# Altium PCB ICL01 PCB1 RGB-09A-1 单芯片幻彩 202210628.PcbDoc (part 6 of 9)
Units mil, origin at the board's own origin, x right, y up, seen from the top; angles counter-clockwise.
Board outline 17436.43 x 6581.89 mil, 2 copper layers (Top Layer, Bottom Layer), stack 65.792 mil thick; 425 components, 516 nets, 1625 pads, 2772 vias.
Unrouted connection lines stored in the file: 1.
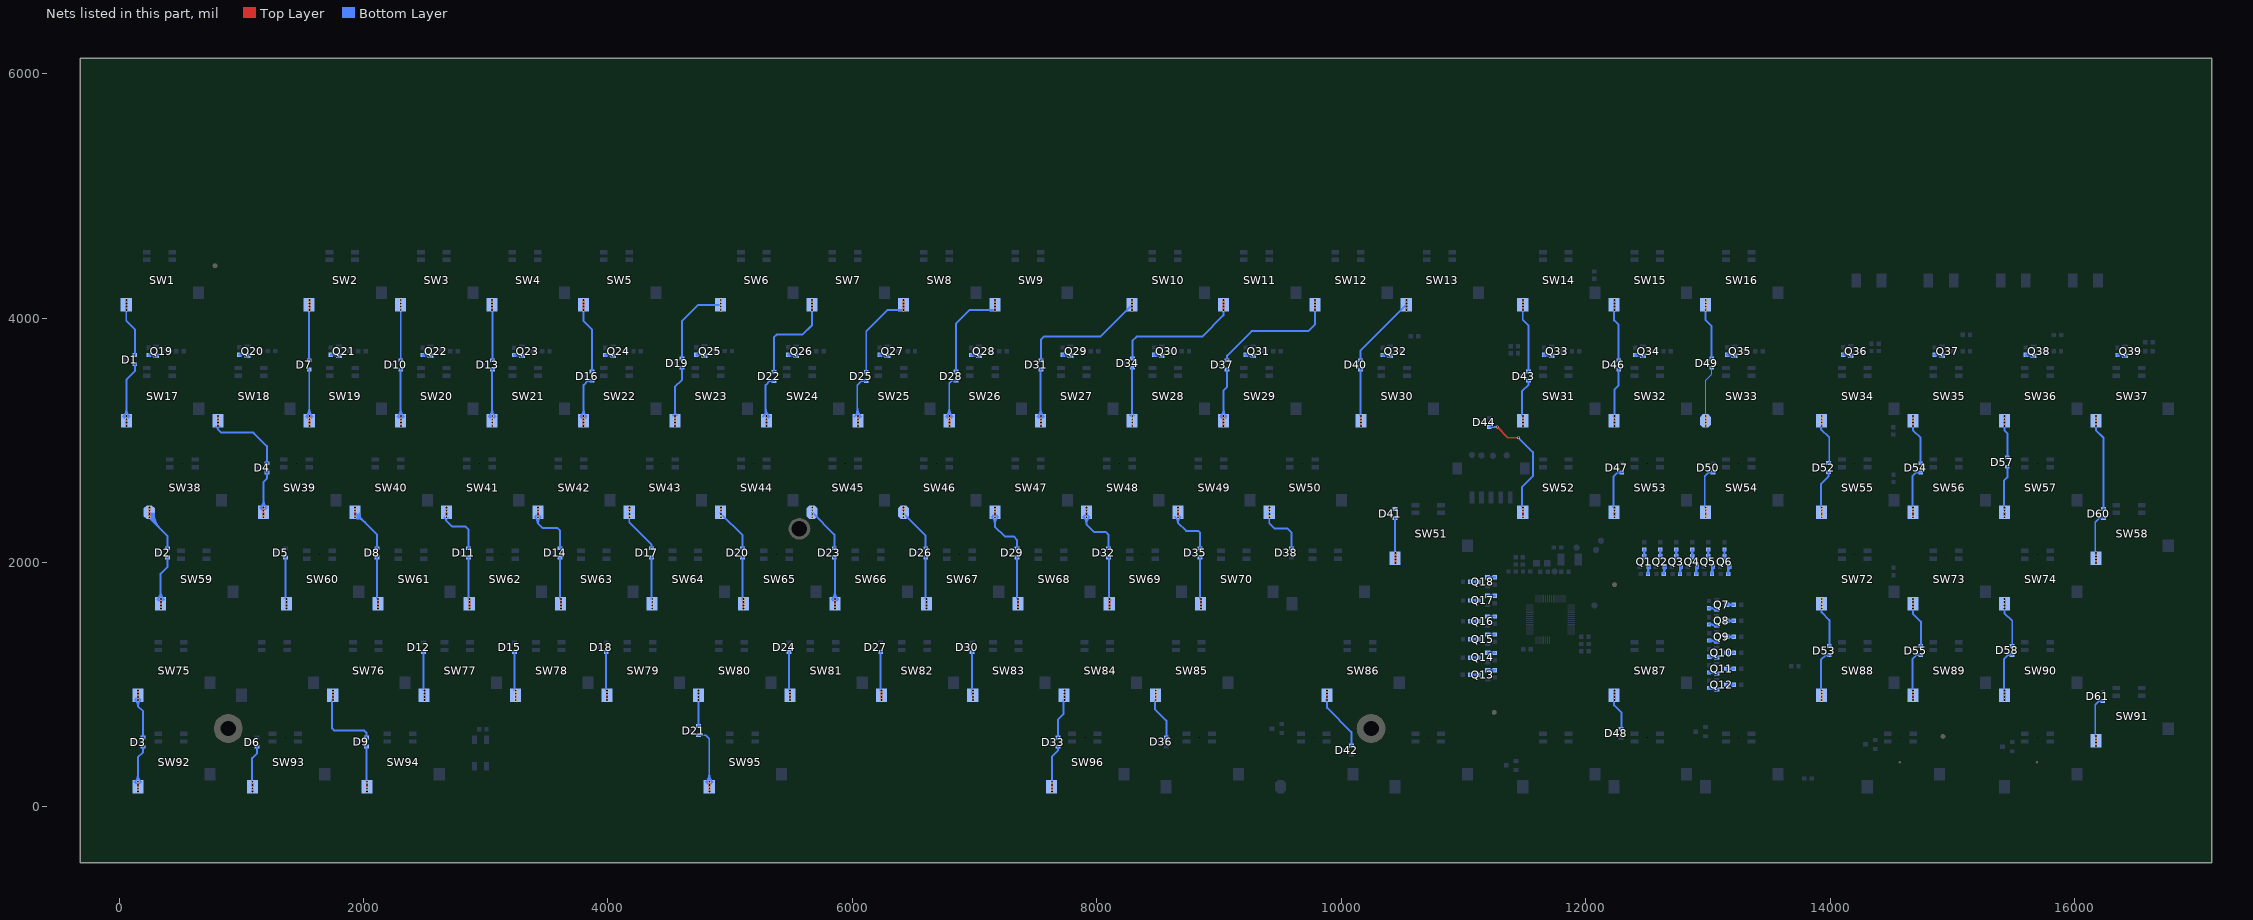
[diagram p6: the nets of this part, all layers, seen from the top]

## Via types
v1: diameter 23.62, hole 15.75, Top Layer to Bottom Layer, tented both sides, 2766 vias
v2: diameter 19.68, hole 11.81, Top Layer to Bottom Layer, tented both sides, 6 vias

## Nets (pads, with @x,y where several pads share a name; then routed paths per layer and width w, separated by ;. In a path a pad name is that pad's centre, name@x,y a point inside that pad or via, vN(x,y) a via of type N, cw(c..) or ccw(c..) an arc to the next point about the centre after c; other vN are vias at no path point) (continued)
NetRL1_2: Q1.B RL1.2 | length 134.2
  Bottom Layer w19.68: RL1.2@12504.25,1912.02 ccw(c12491.5,1924.77) 12509.53,1924.77 ; RL1.2@12509.53,1901.98 12509.53,1960.16 Q1.B@12517.01,1967.65 ; 12509.53,1926.16 ccw(c12529.52,1926.16) RL1.2@12515.38,1912.02 ; 12509.53,1926.22 cw(c12554.79,1926.22) Q1.B@12522.78,1958.22
NetRL2_2: Q2.B RL2.2 | length 121.1
  Bottom Layer w19.68: RL2.2@12634.17,1911.04 ccw(c12619.05,1926.16) 12640.43,1926.16 ; RL2.2@12640.43,1901.98 12640.43,1960.16 Q2.B@12647.92,1967.65 ; 12640.43,1926.22 cw(c12685.69,1926.22) Q2.B@12653.69,1958.22
NetRL3_2: Q3.B RL3.2 | length 121.1
  Bottom Layer w19.68: RL3.2@12766.06,1911.04 ccw(c12750.93,1926.17) 12772.32,1926.17 ; RL3.2@12772.32,1901.98 12772.32,1960.16 Q3.B@12779.81,1967.65 ; 12772.32,1926.22 cw(c12817.58,1926.22) Q3.B@12785.58,1958.22
NetRL4_2: Q4.B RL4.2 | length 134.2
  Bottom Layer w19.68: RL4.2@12897.95,1912.03 ccw(c12885.2,1924.77) 12903.23,1924.77 ; RL4.2@12903.23,1901.98 12903.23,1960.16 Q4.B@12910.72,1967.65 ; 12903.23,1926.16 ccw(c12923.22,1926.16) RL4.2@12909.08,1912.03 ; 12903.23,1926.22 cw(c12948.49,1926.22) Q4.B@12916.48,1958.22
NetRL5_2: Q5.B RL5.2 | length 121.1
  Bottom Layer w19.68: RL5.2@13027.87,1913.01 ccw(c13012.74,1928.13) 13034.13,1928.13 ; RL5.2@13034.13,1901.98 13034.13,1960.16 Q5.B@13041.62,1967.65 ; 13034.13,1926.22 cw(c13079.39,1926.22) Q5.B@13047.39,1958.22
NetRL6_2: Q6.B RL6.2 | length 121.1
  Bottom Layer w19.68: RL6.2@13159.76,1912.03 ccw(c13144.63,1927.15) 13166.02,1927.15 ; RL6.2@13166.02,1901.98 13166.02,1960.16 Q6.B@13173.51,1967.65 ; 13166.02,1926.22 cw(c13211.28,1926.22) Q6.B@13179.28,1958.22
NetRL7_2: Q7.B RL7.2 | length 121.1
  Bottom Layer w19.68: RL7.2@13007.2,1623.93 13065.39,1623.93 Q7.B@13072.87,1616.44 ; RL7.2@13014.3,1630.2 ccw(c13029.42,1645.32) 13029.42,1623.93 ; 13031.45,1623.93 cw(c13031.45,1578.67) Q7.B@13063.45,1610.68
NetRL8_2: Q8.B RL8.2 | length 121.1
  Bottom Layer w19.68: RL8.2@13007.56,1492.53 13065.74,1492.53 Q8.B@13073.23,1485.04 ; RL8.2@13014.65,1498.79 ccw(c13029.78,1513.92) 13029.78,1492.53 ; 13031.8,1492.53 cw(c13031.8,1447.27) Q8.B@13063.81,1479.27
NetRL9_2: Q9.B RL9.2 | length 122.1
  Bottom Layer w19.68: RL9.2@13007.56,1360.64 13065.74,1360.64 Q9.B@13073.23,1353.15 ; RL9.2@13015.79,1367.26 ccw(c13031.78,1383.25) 13031.78,1360.64 ; 13031.8,1360.64 cw(c13031.8,1315.38) Q9.B@13063.81,1347.38
NetRL10_2: Q10.B RL10.2 | length 134.2
  Bottom Layer w19.68: RL10.2@13007.56,1229.73 13065.74,1229.73 Q10.B@13073.23,1222.24 ; RL10.2@13017.61,1223.88 cw(c13031.74,1209.74) 13031.74,1229.73 ; RL10.2@13017.61,1235.01 ccw(c13030.36,1247.76) 13030.36,1229.73 ; 13031.8,1229.73 cw(c13031.8,1184.47) Q10.B@13063.81,1216.48
NetRL11_2: Q11.B RL11.2 | length 121.1
  Bottom Layer w19.68: RL11.2@13007.56,1098.83 13065.74,1098.83 Q11.B@13073.23,1091.34 ; RL11.2@13014.65,1105.09 ccw(c13029.78,1120.21) 13029.78,1098.83 ; 13031.8,1098.83 cw(c13031.8,1053.56) Q11.B@13063.81,1085.57
NetRL12_2: Q12.B RL12.2 | length 131.7
  Bottom Layer w19.68: RL12.2@13007.56,967.92 13065.74,967.92 Q12.B@13073.23,960.43 ; RL12.2@13013.67,978.12 ccw(c13038.3,1002.75) 13038.3,967.92 ; 13031.8,967.92 cw(c13031.8,922.66) Q12.B@13063.81,954.66
NetRL13_2: Q13.B RL13.2 | length 58
  Bottom Layer w19.68: Q13.B@11196.58,1119.6 RL13.2@11254.57,1119.6
NetRL14_2: Q14.B RL14.2 | length 58
  Bottom Layer w19.68: Q14.B@11196.58,1260.23 RL14.2@11254.57,1260.23
NetRL15_2: Q15.B RL15.2 | length 58
  Bottom Layer w19.68: Q15.B@11196.58,1410.85 RL15.2@11254.57,1410.85
NetRL16_2: Q16.B RL16.2 | length 58
  Bottom Layer w19.68: Q16.B@11196.58,1558.37 RL16.2@11254.57,1558.37
NetRL17_2: Q17.B RL17.2 | length 58
  Bottom Layer w19.68: Q17.B@11196.58,1727.44 RL17.2@11254.57,1727.44
NetRL18_2: Q18.B RL18.2 | length 58
  Bottom Layer w19.68: Q18.B@11196.58,1878.18 RL18.2@11254.57,1878.18
NetRL19_2: Q19.B RL19.2 | length 128.3
  Bottom Layer w19.68: RL19.2@242.98,3697.46 298.44,3697.46 Q19.B@305.16,3690.75 ; RL19.2@248.55,3691.9 cw(c261.99,3678.45) 261.99,3697.46 cw(c261.99,3716.47) RL19.2@248.55,3703.03 ; 263.63,3697.46 cw(c263.63,3654.84) Q19.B@293.77,3684.98
NetRL20_2: Q20.B RL20.2 | length 135.8
  Bottom Layer w19.68: RL20.2@985.11,3699.92 1042.05,3699.92 Q20.B@1050.24,3691.73 ; RL20.2@990.68,3694.35 cw(c1004.12,3680.91) 1004.12,3699.92 cw(c1004.12,3718.93) RL20.2@990.68,3705.48 ; 1005.16,3699.92 cw(c1005.16,3652.28) Q20.B@1038.84,3685.96
NetRL21_2: Q21.B RL21.2 | length 126.1
  Bottom Layer w19.68: RL21.2@1734.13,3699.92 1791.07,3699.92 Q21.B@1799.25,3691.73 ; RL21.2@1737.72,3693.37 cw(c1753.54,3677.55) 1753.54,3699.92 ; 1751.8,3699.92 cw(c1751.8,3648.92) Q21.B@1787.86,3684.98
NetRL22_2: Q22.B RL22.2 | length 156.3
  Bottom Layer w19.68: RL22.2@2483.14,3699.92 2540.08,3699.92 Q22.B@2548.27,3691.73 ; RL22.2@2490.43,3691.38 cw(c2508.34,3664.23) 2516.76,3695.64 ; RL22.2@2491.66,3692.38 cw(c2509.85,3674.19) 2509.85,3699.92 ; RL22.2@2500.81,3699.92 cw(c2500.81,3648.92) Q22.B@2536.88,3684.98
NetRL23_2: Q23.B RL23.2 | length 158
  Bottom Layer w19.68: RL23.2@3232.16,3699.92 3289.1,3699.92 Q23.B@3297.28,3691.73 ; RL23.2@3236.52,3691.39 cw(c3255.59,3662.75) 3264.49,3695.99 ; RL23.2@3237.72,3692.38 cw(c3255.92,3674.19) 3255.92,3699.92 ; RL23.2@3249.83,3699.92 cw(c3249.83,3648.92) Q23.B@3285.89,3684.98
NetRL24_2: Q24.B RL24.2 | length 128.8
  Bottom Layer w19.68: RL24.2@3979.2,3699.92 4036.14,3699.92 Q24.B@4044.33,3691.73 ; RL24.2@3983.79,3692.38 cw(c4001.98,3674.19) 4001.98,3699.92 ; 3996.88,3699.92 cw(c3996.88,3648.92) Q24.B@4032.94,3684.98
NetRL25_2: Q25.B RL25.2 | length 133.2
  Bottom Layer w19.68: RL25.2@4726.25,3699.92 4783.19,3699.92 Q25.B@4791.38,3691.73 ; RL25.2@4727.88,3694.35 cw(c4741.32,3680.91) 4741.32,3699.92 cw(c4741.32,3718.93) RL25.2@4727.88,3705.48 ; 4748.68,3699.92 cw(c4748.68,3655.64) Q25.B@4779.99,3686.95
NetRL26_2: Q26.B RL26.2 | length 165.6
  Bottom Layer w19.68: RL26.2@5475.27,3699.92 5532.21,3699.92 Q26.B@5540.39,3691.73 ; RL26.2@5479.2,3693.1 cw(c5496.52,3663.11) 5505.48,3696.56 ; RL26.2@5480.83,3694.35 cw(c5494.28,3680.91) 5494.28,3699.92 cw(c5494.28,3718.93) RL26.2@5480.83,3705.48 ; RL26.2@5492.94,3699.92 cw(c5492.94,3648.92) Q26.B@5529,3684.98
NetRL27_2: Q27.B RL27.2 | length 154.5
  Bottom Layer w19.68: RL27.2@6221.33,3699.92 6278.27,3699.92 Q27.B@6286.46,3691.73 ; RL27.2@6227.24,3692.11 cw(c6245.3,3660.82) 6254.65,3695.72 ; RL27.2@6228.87,3693.37 cw(c6244.68,3677.55) 6244.68,3699.92 ; RL27.2@6239,3699.92 cw(c6239,3648.92) Q27.B@6275.06,3684.98
NetRL28_2: Q28.B RL28.2 | length 156.3
  Bottom Layer w19.68: RL28.2@6970.35,3699.92 7027.29,3699.92 Q28.B@7035.47,3691.73 ; RL28.2@6977.64,3691.38 cw(c6995.55,3664.23) 7003.96,3695.64 ; RL28.2@6978.87,3692.38 cw(c6997.06,3674.19) 6997.06,3699.92 ; RL28.2@6988.02,3699.92 cw(c6988.02,3648.92) Q28.B@7024.08,3684.98
NetRL29_2: Q29.B RL29.2 | length 155.9
  Bottom Layer w19.68: RL29.2@7720.35,3699.92 7777.29,3699.92 Q29.B@7785.47,3691.73 ; RL29.2@7724.28,3692.11 cw(c7743.22,3659.32) 7753.02,3695.9 ; RL29.2@7725.91,3693.37 cw(c7741.73,3677.55) 7741.73,3699.92 ; RL29.2@7738.02,3699.92 cw(c7738.02,3648.92) Q29.B@7774.08,3684.98
NetRL30_2: Q30.B RL30.2 | length 153.8
  Bottom Layer w19.68: RL30.2@8466.41,3699.92 8523.35,3699.92 Q30.B@8531.53,3691.73 ; RL30.2@8473.3,3692.11 cw(c8490.93,3661.58) 8500.06,3695.64 ; RL30.2@8474.93,3693.37 cw(c8490.75,3677.55) 8490.75,3699.92 ; RL30.2@8484.08,3699.92 cw(c8484.08,3648.92) Q30.B@8520.14,3684.98
NetRL31_2: Q31.B RL31.2 | length 153.2
  Bottom Layer w19.68: RL31.2@9214.44,3699.92 9271.38,3699.92 Q31.B@9279.57,3691.73 ; RL31.2@9222.31,3692.11 cw(c9239.51,3662.33) 9248.41,3695.55 ; RL31.2@9223.94,3693.37 cw(c9239.76,3677.55) 9239.76,3699.92 ; RL31.2@9232.11,3699.92 cw(c9232.11,3648.92) Q31.B@9268.17,3684.98
NetRL32_2: Q32.B RL32.2 | length 156.3
  Bottom Layer w19.68: RL32.2@10336.49,3699.92 10393.43,3699.92 Q32.B@10401.61,3691.73 ; RL32.2@10343.78,3691.38 cw(c10361.69,3664.23) 10370.1,3695.65 ; RL32.2@10345.01,3692.38 cw(c10363.2,3674.19) 10363.2,3699.92 ; RL32.2@10354.16,3699.92 cw(c10354.16,3648.92) Q32.B@10390.22,3684.98
NetRL33_2: Q33.B RL33.2 | length 154.5
  Bottom Layer w19.68: RL33.2@11656.37,3699.92 11713.31,3699.92 Q33.B@11721.5,3691.73 ; RL33.2@11662.27,3692.11 cw(c11680.34,3660.82) 11689.69,3695.72 ; RL33.2@11663.91,3693.37 cw(c11679.72,3677.55) 11679.72,3699.92 ; RL33.2@11674.04,3699.92 cw(c11674.04,3648.92) Q33.B@11710.1,3684.98
NetRL34_2: Q34.B RL34.2 | length 158
  Bottom Layer w19.68: RL34.2@12404.4,3699.92 12461.34,3699.92 Q34.B@12469.53,3691.73 ; RL34.2@12408.76,3691.39 cw(c12427.83,3662.75) 12436.74,3695.99 ; RL34.2@12409.97,3692.38 cw(c12428.16,3674.19) 12428.16,3699.92 ; RL34.2@12422.07,3699.92 cw(c12422.07,3648.92) Q34.B@12458.14,3684.98
NetRL35_2: Q35.B RL35.2 | length 146.4
  Bottom Layer w19.68: RL35.2@13152.43,3699.92 13209.37,3699.92 Q35.B@13217.56,3691.73 ; RL35.2@13161.29,3694.08 cw(c13175.86,3668.85) 13183.4,3696.99 ; RL35.2@13162.92,3706.47 ccw(c13178.74,3722.29) 13178.74,3699.92 ; RL35.2@13172.48,3699.92 cw(c13172.48,3652.28) Q35.B@13206.17,3685.96
NetRL36_2: Q36.B RL36.2 | length 120.9
  Bottom Layer w19.68: RL36.2@14104.2,3699.92 14161.14,3699.92 Q36.B@14169.33,3691.73 ; RL36.2@14111.74,3706.47 ccw(c14127.56,3722.29) 14127.56,3699.92 ; 14126.63,3699.92 cw(c14126.63,3655.64) Q36.B@14157.94,3686.95
NetRL37_2: Q37.B RL37.2 | length 123.5
  Bottom Layer w19.68: RL37.2@14851.25,3699.92 14908.19,3699.92 Q37.B@14916.38,3691.73 ; RL37.2@14858.79,3693.37 cw(c14874.61,3677.55) 14874.61,3699.92 ; 14871.3,3699.92 cw(c14871.3,3652.28) Q37.B@14904.99,3685.96
NetRL38_2: Q38.B RL38.2 | length 153.8
  Bottom Layer w19.68: RL38.2@15598.3,3699.92 15655.24,3699.92 Q38.B@15663.42,3691.73 ; RL38.2@15605.19,3692.11 cw(c15622.82,3661.57) 15631.95,3695.64 ; RL38.2@15606.82,3693.37 cw(c15622.64,3677.55) 15622.64,3699.92 ; RL38.2@15615.97,3699.92 cw(c15615.97,3648.92) Q38.B@15652.03,3684.98
NetRL39_2: Q39.B RL39.2 | length 129.8
  Bottom Layer w19.68: RL39.2@16350.27,3697.95 16405.24,3697.95 Q39.B@16412.44,3690.75 ; RL39.2@16355.83,3692.38 cw(c16369.28,3678.94) 16369.28,3697.95 cw(c16369.28,3716.96) RL39.2@16355.83,3703.52 ; 16369.74,3697.95 cw(c16369.74,3653.67) Q39.B@16401.05,3684.98
NetRR1_1: Q1.C RR1.1 | length 58
  Bottom Layer w19.68: Q1.C@12479.01,2047.65 RR1.1@12479.01,2105.61
NetRR2_1: Q2.C RR2.1 | length 58
  Bottom Layer w19.68: Q2.C@12609.92,2047.65 RR2.1@12609.92,2105.61
NetRR3_1: Q3.C RR3.1 | length 58
  Bottom Layer w19.68: Q3.C@12741.81,2047.65 RR3.1@12741.81,2105.61
NetRR4_1: Q4.C RR4.1 | length 58
  Bottom Layer w19.68: Q4.C@12872.72,2047.65 RR4.1@12872.69,2105.61
NetRR5_1: Q5.C RR5.1 | length 58
  Bottom Layer w19.68: Q5.C@13003.62,2047.65 RR5.1@13003.62,2105.61
NetRR6_1: Q6.C RR6.1 | length 58
  Bottom Layer w19.68: Q6.C@13135.51,2047.65 RR6.1@13135.51,2105.61
NetRR7_1: Q7.C RR7.1 | length 59.5
  Bottom Layer w19.68: Q7.C@13152.87,1654.44 RR7.1@13212.34,1654.44
NetRR8_1: Q8.C RR8.1 | length 59.1
  Bottom Layer w19.68: Q8.C@13153.23,1523.04 RR8.1@13212.34,1523.08
NetRR9_1: Q9.C RR9.1 | length 59.1
  Bottom Layer w19.68: Q9.C@13153.23,1391.15 RR9.1@13212.34,1391.15
NetRR10_1: Q10.C RR10.1 | length 59.1
  Bottom Layer w19.68: Q10.C@13153.23,1260.24 RR10.1@13212.34,1260.24
NetRR11_1: Q11.C RR11.1 | length 59.1
  Bottom Layer w19.68: Q11.C@13153.23,1129.34 RR11.1@13212.34,1129.34
NetRR12_1: Q12.C RR12.1 | length 59.1
  Bottom Layer w19.68: Q12.C@13153.23,998.43 RR12.1@13212.34,998.43
NetRR13_1: Q13.C RR13.1 | length 64.2
  Bottom Layer w19.68: RR13.1@11055.07,1082.02 Q13.C@11119.23,1082.02
NetRR14_1: Q14.C RR14.1 | length 63.8
  Bottom Layer w19.68: RR14.1@11055.09,1222.3 Q14.C@11118.87,1222.3
NetRR15_1: Q15.C RR15.1 | length 63.7
  Bottom Layer w19.68: RR15.1@11055.55,1373.12 Q15.C@11119.23,1373.12
NetRR16_1: Q16.C RR16.1 | length 61
  Bottom Layer w19.68: RR16.1@11055.53,1520.37 Q16.C@11116.58,1520.37
NetRR17_1: Q17.C RR17.1 | length 61.1
  Bottom Layer w19.68: RR17.1@11055.5,1689.42 Q17.C@11116.58,1689.42
NetRR18_1: Q18.C RR18.1 | length 61
  Bottom Layer w19.68: RR18.1@11055.6,1842.12 Q18.C@11116.58,1842.12
NetSW1_2: D1.K1 SW1.2 | length 519.2
  Top Layer w15.75: v1(60.78,4067.09) v1(60.78,4147.08)
  Bottom Layer w15.75: SW1.2@59.52,4107.08 59.52,3977.97 129.23,3908.26 D1.K1@129.23,3696.72
  other v1: 60.78,4093.75 60.78,4120.42
NetSW2_2: D7.K1 SW2.2 | length 492.7
  Top Layer w15.75: v1(1556.84,4067.09) v1(1556.84,4093.75) v1(1556.84,4120.42) ; v1@1557.5,4120.41 v1@1557.83,4147.07
  Bottom Layer w15.75: D7.K1@1555.58,3654.37 SW2.2@1555.58,4067.09
  other v1: 1556.84,4147.08
NetSW3_2: D10.K1 SW3.2 | length 493.1
  Top Layer w15.75: v1(2304.87,4147.08) v1(2304.87,4120.42) v1(2304.87,4093.75) 2304.87,4068.07 v1@2305.86,4067.09
  Bottom Layer w15.75: D10.K1@2305.38,3654.37 SW3.2@2305.38,4067.09
  other v1: 2304.87,4067.09
NetSW4_2: D13.K1 SW4.2 | length 492.7
  Top Layer w15.75: v1(3052.9,4067.09) v1(3052.9,4093.75) v1(3052.9,4120.42) v1(3052.9,4147.08)
  Bottom Layer w15.75: D13.K1@3056.25,3654.37 SW4.2@3056.25,4067.09
NetSW5_2: D16.K1 SW5.2 | length 613.8
  Top Layer w15.75: v1(3800.94,4067.09) v1(3800.94,4093.75) v1(3800.94,4120.42) v1(3800.94,4147.08)
  Bottom Layer w15.75: SW5.2@3799.68,4067.09 3799.68,3976.98 3869.41,3907.25 D16.K1@3869.41,3562.15
NetSW6_2: D19.K1 SW6.2 | length 758
  Top Layer w15.75: v1(4922.98,4067.09) v1(4922.98,4093.75) v1(4922.98,4120.42) v1(4922.98,4147.08)
  Bottom Layer w15.75: D19.K1@4605.63,3667.82 4605.63,3974.94 4737.77,4107.08 SW6.2@4921.72,4107.08
NetSW7_2: D22.K1 SW7.2 | length 839.1
  Top Layer w15.75: v1(5671.02,4067.09) v1(5671.02,4093.75) v1(5671.02,4120.42) v1(5671.02,4147.08)
  Bottom Layer w15.75: D22.K1@5358.17,3560.73 5358.17,3840.96 5380.81,3863.59 5591.97,3863.59 5669.76,3941.37 SW7.2@5669.76,4067.09
NetSW8_2: D25.K1 SW8.2 | length 787.7
  Top Layer w15.75: v1(6419.05,4067.09) v1(6419.05,4093.75) v1(6419.05,4120.42) v1(6419.05,4147.08)
  Bottom Layer w15.75: D25.K1@6113.5,3561.17 6113.5,3892.03 6288.56,4067.09 SW8.2@6417.79,4067.09
NetSW9_2: D28.K1 SW9.2 | length 838.1
  Top Layer w15.75: v1(7167.08,4067.09) v1(7167.08,4093.75) v1(7167.08,4120.42) v1(7167.08,4147.08)
  Bottom Layer w15.75: D28.K1@6848.51,3561.83 6848.51,3957.02 6958.57,4067.09 SW9.2@7165.82,4067.09
NetSW10_2: D31.K1 SW10.2 | length 1103.8
  Top Layer w15.75: v1(8289.13,4147.08) v1(8289.13,4120.42) v1(8289.13,4093.75) 8289.13,4068.07 v1@8290.11,4067.09
  Bottom Layer w15.75: D31.K1@7543.87,3654.76 7543.87,3826.42 7566.27,3848.83 8029.61,3848.83 SW10.2@8281.83,4101.05
  other v1: 8289.13,4067.09
NetSW11_2: D34.K1 SW11.2 | length 1101.5
  Top Layer w15.75: v1(9037.16,4067.09) v1(9037.16,4093.75) v1(9037.16,4120.42) v1(9037.16,4147.08)
  Bottom Layer w15.75: D34.K1@8291.3,3667.66 8291.3,3812.77 8326.37,3847.84 8861.77,3847.84 9035.9,4021.97 SW11.2@9035.9,4067.09
NetSW12_2: D37.K1 SW12.2 | length 1102.3
  Top Layer w15.75: v1(9785.19,4067.09) v1(9785.19,4093.75) v1(9785.19,4120.42) v1(9785.19,4147.08)
  Bottom Layer w15.75: D37.K1@9066.26,3654.37 9066.26,3691.98 9267.04,3892.75 9731.83,3892.75 9783.93,3944.85 SW12.2@9783.93,4107.08
NetSW13_2: D40.K1 SW13.2 | length 680
  Top Layer w15.75: v1(10533.22,4147.08) v1(10533.22,4120.42) v1(10533.22,4093.75) 10533.22,4068.07 v1@10534.2,4067.09
  Bottom Layer w15.75: D40.K1@10158.34,3654.37 10158.34,3735.82 SW13.2@10524.74,4102.23
  other v1: 10533.22,4067.09
NetSW14_2: D43.K1 SW14.2 | length 605.5
  Top Layer w15.75: v1(11485.98,4067.09) v1(11485.98,4093.75) v1(11485.98,4120.42) v1(11485.98,4147.08)
  Bottom Layer w15.75: SW14.2@11484.72,4067.09 11484.72,3985.84 11532.69,3937.87 D43.K1@11532.69,3561.47
NetSW15_2: D46.K1 SW15.2 | length 508.1
  Top Layer w15.75: v1(12234.01,4067.09) v1(12234.01,4093.75) v1(12234.01,4120.42) v1(12234.01,4147.08)
  Bottom Layer w15.75: SW15.2@12232.75,4067.09 12232.75,3980.92 12269.77,3943.9 D46.K1@12269.77,3654.37
NetSW16_2: D49.K1 SW16.2 | length 500
  Top Layer w15.75: v1(12982.04,4067.09) v1(12982.04,4093.75) v1(12982.04,4120.42) v1(12982.04,4147.08)
  Bottom Layer w15.75: SW16.2@12980.78,4067.09 12980.78,3982.89 13030.83,3932.84 D49.K1@13030.83,3667.82
NetSW17_2: D1.K2 SW17.2 | length 816.1
  Top Layer w15.75: v1(61.76,3118.27) v1(61.76,3144.93) v1(61.76,3171.6) v1(61.76,3198.27)
  Bottom Layer w15.75: SW17.2@34.06,3194.56 ccw(c-29.79,3258.4) 60.5,3258.4 ccw(c150.8,3258.4) SW17.2@86.95,3194.56 ; SW17.2@44.94,3183.05 cw(c67.4,3167.55) SW17.2@62.47,3194.39 ; SW17.2@45.19,3183.42 ccw(c8.23,3220.38) 60.5,3220.38 ccw(c112.78,3220.38) SW17.2@75.81,3183.42 ; SW17.2@58.93,3201 ccw(c49.59,3209.99) SW17.2@62.23,3212.9 ; SW17.2@60.5,3198.27 60.5,3495.6 129.23,3564.32 D1.K2@129.23,3621.72 ; SW17.2@60.5,3210.81 ccw(c74.31,3210.81) SW17.2@64.55,3201.05 ; SW17.2@61.11,3194.38 cw(c57.93,3175.47) SW17.2@73.55,3186.6
NetSW18_2: D4.K1 SW18.2 | length 823.3
  Top Layer w15.75: v1(809.8,3118.27) v1(809.8,3144.93) v1(809.8,3171.6) v1(809.8,3198.27)
  Bottom Layer w15.75: SW18.2@793.27,3114.28 cw(c783.28,3091.93) 807.75,3091.93 cw(c831.23,3091.93) SW18.2@822.48,3113.72 ; SW18.2@807.35,3115.18 cw(c798.99,3104.65) 811.08,3098.75 ; SW18.2@807.75,3103.83 cw(c824.23,3103.83) SW18.2@812.58,3115.48 ; SW18.2@807.75,3118.27 807.75,3091.94 837.38,3062.31 1099.76,3062.31 1210.31,2951.76 D4.K1@1210.31,2812.51 ; D4.K1@1204.75,2818.08 ccw(c1191.3,2831.52) 1210.31,2831.52 ccw(c1229.32,2831.52) D4.K1@1215.88,2818.08
NetSW19_2: D7.K2 SW19.2 | length 745.3
  Top Layer w15.75: v1(1557.83,3118.27) v1(1557.83,3144.93) v1(1557.83,3171.6) v1(1557.83,3198.27)
  Bottom Layer w15.75: SW19.2@1530.12,3194.56 ccw(c1466.27,3258.4) 1556.57,3258.4 ccw(c1646.86,3258.4) SW19.2@1583.01,3194.56 ; SW19.2@1541,3183.05 cw(c1563.46,3167.55) SW19.2@1558.54,3194.39 ; SW19.2@1541.25,3183.42 ccw(c1504.29,3220.38) 1556.57,3220.38 ccw(c1608.84,3220.38) SW19.2@1571.88,3183.42 ; SW19.2@1554.99,3201 ccw(c1545.66,3209.99) SW19.2@1558.29,3212.9 ; SW19.2@1556.57,3198.27 D7.K2@1556.57,3579.37 ; SW19.2@1556.57,3210.81 ccw(c1570.37,3210.81) SW19.2@1560.61,3201.05 ; SW19.2@1557.17,3194.38 cw(c1554,3175.47) SW19.2@1569.61,3186.6
NetSW20_2: D10.K2 SW20.2 | length 745.3
  Top Layer w15.75: v1(2305.86,3118.27) v1(2305.86,3144.93) v1(2305.86,3171.6) v1(2305.86,3198.27)
  Bottom Layer w15.75: SW20.2@2278.15,3194.56 ccw(c2214.3,3258.4) 2304.6,3258.4 ccw(c2394.89,3258.4) SW20.2@2331.04,3194.56 ; SW20.2@2289.03,3183.05 cw(c2311.49,3167.55) SW20.2@2306.57,3194.39 ; SW20.2@2289.29,3183.42 ccw(c2252.32,3220.38) 2304.6,3220.38 ccw(c2356.87,3220.38) SW20.2@2319.91,3183.42 ; SW20.2@2303.02,3201 ccw(c2293.69,3209.99) SW20.2@2306.32,3212.9 ; SW20.2@2304.6,3198.27 D10.K2@2304.6,3579.37 ; SW20.2@2304.6,3210.81 ccw(c2318.4,3210.81) SW20.2@2308.64,3201.05 ; SW20.2@2305.21,3194.38 cw(c2302.03,3175.47) SW20.2@2317.65,3186.6
NetSW21_2: D13.K2 SW21.2 | length 745.3
  Top Layer w15.75: v1(3053.89,3118.27) v1(3053.89,3144.93) v1(3053.89,3171.6) v1(3053.89,3198.27)
  Bottom Layer w15.75: SW21.2@3026.18,3194.56 ccw(c2962.33,3258.4) 3052.63,3258.4 ccw(c3142.92,3258.4) SW21.2@3079.08,3194.56 ; SW21.2@3037.06,3183.05 cw(c3059.52,3167.55) SW21.2@3054.6,3194.39 ; SW21.2@3037.32,3183.42 ccw(c3000.35,3220.38) 3052.63,3220.38 ccw(c3104.91,3220.38) SW21.2@3067.94,3183.42 ; SW21.2@3051.05,3201 ccw(c3041.72,3209.99) SW21.2@3054.35,3212.9 ; SW21.2@3052.63,3198.27 D13.K2@3052.63,3579.37 ; SW21.2@3052.63,3210.81 ccw(c3066.44,3210.81) SW21.2@3056.67,3201.05 ; SW21.2@3053.24,3194.38 cw(c3050.06,3175.47) SW21.2@3065.68,3186.6
NetSW22_2: D16.K2 SW22.2 | length 730.8
  Top Layer w15.75: v1(3801.92,3118.27) v1(3801.92,3144.93) v1(3801.92,3171.6) v1(3801.92,3198.27)
  Bottom Layer w15.75: SW22.2@3774.21,3194.56 ccw(c3710.37,3258.4) 3800.66,3258.4 ccw(c3890.96,3258.4) SW22.2@3827.11,3194.56 ; SW22.2@3785.09,3183.05 cw(c3807.56,3167.55) SW22.2@3802.63,3194.39 ; SW22.2@3785.35,3183.42 ccw(c3748.38,3220.38) 3800.66,3220.38 ccw(c3852.94,3220.38) SW22.2@3815.97,3183.42 ; SW22.2@3799.09,3201 ccw(c3789.75,3209.99) SW22.2@3802.38,3212.9 ; SW22.2@3800.66,3198.27 3800.66,3450.99 3836.2,3486.52 D16.K2@3870.04,3486.52 ; SW22.2@3800.66,3210.81 ccw(c3814.47,3210.81) SW22.2@3804.7,3201.05 ; SW22.2@3801.27,3194.38 cw(c3798.09,3175.47) SW22.2@3813.71,3186.6 ; D16.K2@3860.53,3480.96 ccw(c3847.09,3467.51) 3847.09,3486.52 ccw(c3847.09,3505.53) D16.K2@3860.53,3492.09
NetSW23_2: D19.K2 SW23.2 | length 612.5
  Top Layer w15.75: v1(4549.95,3118.27) v1(4549.95,3144.93) v1(4549.95,3171.6) v1(4549.95,3198.27)
  Bottom Layer w15.75: SW23.2@4534.08,3202.54 ccw(c4524.72,3224.61) 4548.69,3224.61 ccw(c4572.66,3224.61) SW23.2@4563.3,3202.54 ; SW23.2@4547.81,3201.57 ccw(c4541.15,3211.84) 4552.24,3217.03 ; SW23.2@4548.69,3198.27 4548.69,3436.05 4605.63,3492.98 D19.K2@4605.63,3592.82 ; SW23.2@4548.69,3210.81 ccw(c4562.5,3210.81) SW23.2@4552.74,3201.05 ; D19.K2@4600.06,3587.26 cw(c4586.62,3573.81) 4605.63,3573.81 cw(c4624.64,3573.81) D19.K2@4611.2,3587.26
NetSW24_2: D22.K2 SW24.2 | length 696.3
  Top Layer w15.75: v1(5297.98,3118.27) v1(5297.98,3144.93) v1(5297.98,3171.6) v1(5297.98,3198.27)
  Bottom Layer w15.75: SW24.2@5270.28,3194.56 ccw(c5220.19,3244.64) 5291.02,3244.64 ; SW24.2@5291.02,3198.27 5291.02,3451.19 5325.56,3485.73 D22.K2@5358.17,3485.73 ; 5291.02,3224.58 ccw(c5324.3,3224.58) SW24.2@5300.77,3201.05 ; 5291.02,3234.15 ccw(c5362.77,3234.15) SW24.2@5312.04,3183.42 ; 5291.02,3272.17 ccw(c5400.79,3272.17) SW24.2@5323.17,3194.56 ; SW24.2@5294.56,3200.22 ccw(c5278.1,3209.6) 5296.38,3214.6 ; SW24.2@5297.49,3194.36 cw(c5295.45,3178.17) SW24.2@5308.35,3188.17 ; D22.K2@5348.67,3480.16 ccw(c5335.23,3466.72) 5335.23,3485.73 ccw(c5335.23,3504.74) D22.K2@5348.67,3491.3
NetSW25_2: D25.K2 SW25.2 | length 697.9
  Top Layer w15.75: v1(6046.02,3118.27) v1(6046.02,3144.93) v1(6046.02,3171.6) v1(6046.02,3198.27)
  Bottom Layer w15.75: SW25.2@6018.31,3194.56 ccw(c5965.85,3247.02) 6040.04,3247.02 ; SW25.2@6040.04,3198.27 6040.04,3450.21 6075.37,3485.54 D25.K2@6114.13,3485.54 ; 6040.04,3222.2 ccw(c6069.95,3222.2) SW25.2@6048.8,3201.05 ; 6040.04,3231.77 ccw(c6108.42,3231.77) SW25.2@6060.07,3183.42 ; 6040.04,3269.79 ccw(c6146.44,3269.79) SW25.2@6071.2,3194.56 ; SW25.2@6042.61,3200.23 ccw(c6025.8,3209.94) 6044.54,3214.96 ; SW25.2@6045.5,3194.36 cw(c6043.32,3177.8) SW25.2@6056.58,3187.97 ; D25.K2@6104.63,3479.97 ccw(c6091.19,3466.53) 6091.19,3485.54 ccw(c6091.19,3504.55) D25.K2@6104.63,3491.11
NetSW26_2: D28.K2 SW26.2 | length 727.1
  Top Layer w15.75: v1(6794.05,3118.27) v1(6794.05,3144.93) v1(6794.05,3171.6) v1(6794.05,3198.27)
  Bottom Layer w15.75: SW26.2@6766.34,3194.56 ccw(c6702.49,3258.4) 6792.79,3258.4 ccw(c6883.08,3258.4) SW26.2@6819.23,3194.56 ; SW26.2@6777.22,3183.05 cw(c6799.68,3167.55) SW26.2@6794.76,3194.39 ; SW26.2@6777.48,3183.42 ccw(c6740.51,3220.38) 6792.79,3220.38 ccw(c6845.06,3220.38) SW26.2@6808.1,3183.42 ; SW26.2@6791.21,3201 ccw(c6781.88,3209.99) SW26.2@6794.51,3212.9 ; SW26.2@6792.79,3198.27 6792.79,3467.63 6811.99,3486.83 D28.K2@6848.51,3486.83 ; SW26.2@6792.79,3210.81 ccw(c6806.59,3210.81) SW26.2@6796.83,3201.05 ; SW26.2@6793.39,3194.38 cw(c6790.22,3175.47) SW26.2@6805.83,3186.6 ; D28.K2@6839,3481.27 ccw(c6825.56,3467.82) 6825.56,3486.83 ccw(c6825.56,3505.84) D28.K2@6839,3492.4
NetSW27_2: D31.K2 SW27.2 | length 746.9
  Top Layer w15.75: v1(7542.08,3118.27) v1(7542.08,3144.93) v1(7542.08,3171.6) v1(7542.08,3198.27)
  Bottom Layer w15.75: SW27.2@7514.37,3194.56 ccw(c7450.52,3258.4) 7540.82,3258.4 ccw(c7631.11,3258.4) SW27.2@7567.26,3194.56 ; SW27.2@7525.25,3183.05 cw(c7547.71,3167.55) SW27.2@7542.79,3194.39 ; SW27.2@7525.51,3183.42 ccw(c7488.54,3220.38) 7540.82,3220.38 ccw(c7593.09,3220.38) SW27.2@7556.13,3183.42 ; SW27.2@7539.24,3201 ccw(c7529.91,3209.99) SW27.2@7542.54,3212.9 ; SW27.2@7540.82,3198.27 7540.82,3576.71 D31.K2@7543.87,3579.76 ; SW27.2@7540.82,3210.81 ccw(c7554.62,3210.81) SW27.2@7544.86,3201.05 ; SW27.2@7541.43,3194.38 cw(c7538.25,3175.47) SW27.2@7553.87,3186.6
NetSW28_2: D34.K2 SW28.2 | length 568.9
  Top Layer w15.75: v1(8290.11,3118.27) v1(8290.11,3144.93) v1(8290.11,3171.6) v1(8290.11,3198.27)
  Bottom Layer w15.75: SW28.2@8273.17,3202.07 ccw(c8261.86,3226.57) 8288.85,3226.57 ccw(c8315.84,3226.57) SW28.2@8304.53,3202.07 ; SW28.2@8287.91,3201.53 ccw(c8280.46,3212.63) 8292.65,3218.09 ; SW28.2@8288.85,3198.27 D34.K2@8288.85,3592.66 ; SW28.2@8288.85,3210.81 ccw(c8302.66,3210.81) SW28.2@8292.89,3201.05 ; D34.K2@8288.85,3590.2 D34.K2@8291.3,3592.66
NetSW29_2: D37.K2 SW29.2 | length 757.4
  Top Layer w15.75: v1(9038.14,3118.27) v1(9038.14,3144.93) v1(9038.14,3171.6) v1(9038.14,3198.27)
  Bottom Layer w15.75: SW29.2@9010.43,3194.56 ccw(c8946.59,3258.4) 9036.88,3258.4 ccw(c9127.18,3258.4) SW29.2@9063.33,3194.56 ; SW29.2@9021.31,3183.05 cw(c9043.78,3167.55) SW29.2@9038.85,3194.39 ; SW29.2@9021.57,3183.42 ccw(c8984.6,3220.38) 9036.88,3220.38 ccw(c9089.16,3220.38) SW29.2@9052.19,3183.42 ; SW29.2@9035.31,3201 ccw(c9025.97,3209.99) SW29.2@9038.6,3212.9 ; SW29.2@9036.88,3198.27 9036.88,3407.57 9066.26,3436.95 D37.K2@9066.26,3579.37 ; SW29.2@9036.88,3210.81 ccw(c9050.69,3210.81) SW29.2@9040.92,3201.05 ; SW29.2@9037.49,3194.38 cw(c9034.31,3175.47) SW29.2@9049.93,3186.6
NetSW30_2: D40.K2 SW30.2 | length 462.6
  Top Layer w15.75: v1@10160.19,3118.27 10163.14,3121.22 v1(10163.14,3144.93) v1(10163.14,3171.6) v1(10163.14,3198.27)
  Bottom Layer w15.75: D40.K2@10158.34,3579.37 10158.93,3578.77 SW30.2@10158.93,3198.27
  other v1: 10163.14,3118.27
NetSW31_2: D43.K2 SW31.2 | length 390.9
  Top Layer w15.75: v1(11485.98,3118.27) v1(11485.98,3144.93) v1(11485.98,3171.6) v1(11485.98,3198.27)
  Bottom Layer w15.75: SW31.2@11477.83,3198.27 11477.83,3400.79 11532.69,3455.65 D43.K2@11532.69,3486.47
NetSW32_2: D46.K2 SW32.2 | length 472.4
  Top Layer w15.75: v1@12234.01,3125.16 v1(12234.01,3144.93) v1(12234.01,3171.6) v1(12234.01,3198.27)
  Bottom Layer w15.75: SW32.2@12225.86,3198.27 12234.01,3206.42 12234.01,3413.04 12269.77,3448.8 D46.K2@12269.77,3579.37
  other v1: 12234.01,3118.27
NetSW33_2: D49.K2 SW33.2 | length 495.3
  Top Layer w15.75: v1(12982.04,3118.27) v1(12982.04,3144.93) v1(12982.04,3171.6) v1(12982.04,3198.27)
  Bottom Layer w7.87: SW33.2@12980.78,3198.27 12980.78,3490.83 13030.83,3540.88 D49.K2@13030.83,3592.82
NetSW34_2: D52.K1 SW34.2 | length 408.9
  Top Layer w15.75: v1@13930.86,3123.19 v1(13930.86,3144.93) v1(13930.86,3171.6) v1(13930.86,3198.27)
  Bottom Layer w15.75: SW34.2@13924.68,3118.27 13924.68,3091.16 13992.44,3023.39 D52.K1@13992.44,2812.51
  other v1: 13930.86,3118.27
NetSW35_2: D54.K1 SW35.2 | length 410.8
  Top Layer w15.75: v1(14678.89,3118.27) v1(14678.89,3144.93) v1(14678.89,3171.6) v1(14678.89,3198.27)
  Bottom Layer w15.75: SW35.2@14677.63,3118.27 14677.63,3083.28 14740.47,3020.44 D54.K1@14740.47,2813.49
NetSW36_2: D57.K1 SW36.2 | length 350
  Top Layer w15.75: v1(15426.92,3118.27) v1(15426.92,3144.93) v1(15426.92,3171.6) v1(15426.92,3198.27)
  Bottom Layer w15.75: SW36.2@15425.66,3118.27 15425.66,3081.31 15449.49,3057.49 D57.K1@15449.49,2858.15
NetSW37_2: D60.K1 SW37.2 | length 787.2
  Top Layer w15.75: v1(16174.95,3118.27) v1(16174.95,3144.93) v1(16174.95,3171.6) v1(16174.95,3198.27)
  Bottom Layer w15.75: SW37.2@16173.69,3118.27 16173.69,3082.3 16237.52,3018.47 D60.K1@16237.52,2437.51
NetSW38_2: D2.K1 SW38.2 | length 776.2
  Top Layer w15.75: v1(248.77,2370.23) v1(248.77,2396.9) v1(248.77,2423.57) v1(248.77,2450.23)
  Bottom Layer w15.75: SW38.2@246.8,2393.49 cw(c232.85,2369.32) SW38.2@259.81,2376.54 ; SW38.2@247.51,2366.75 397.95,2216.31 D2.K1@397.95,2116.94 ; SW38.2@247.81,2366.42 cw(c238.11,2327.94) 272.17,2348.29 ; SW38.2@252.71,2370.23 ccw(c273.67,2370.23) SW38.2@258.85,2355.41 ; SW38.2@253.42,2400.39 ccw(c348.9,2400.39) 281.38,2332.88 ; SW38.2@269.16,2400.39 ccw(c402.67,2400.39) 308.27,2305.99 ; SW38.2@284.91,2400.39 ccw(c456.43,2400.39) 335.15,2279.11
NetSW39_2: D4.K2 SW39.2 | length 692.8
  Top Layer w15.75: v1(1183.81,2370.23) v1(1183.81,2396.9) v1(1183.81,2423.57) v1(1183.81,2450.23)
  Bottom Layer w15.75: SW39.2@1156.1,2446.52 ccw(c1092.25,2510.37) 1182.55,2510.37 ccw(c1272.84,2510.37) SW39.2@1209,2446.52 ; SW39.2@1166.98,2435.02 cw(c1189.44,2419.52) SW39.2@1184.52,2446.36 ; SW39.2@1167.24,2435.39 ccw(c1130.27,2472.36) 1182.55,2472.36 ccw(c1234.82,2472.35) SW39.2@1197.86,2435.39 ; SW39.2@1180.98,2452.97 ccw(c1171.65,2461.96) SW39.2@1184.27,2464.86 ; SW39.2@1182.55,2450.23 1182.55,2658.58 1210.31,2686.34 D4.K2@1210.31,2737.51 ; SW39.2@1182.55,2462.78 ccw(c1196.35,2462.78) SW39.2@1186.59,2453.02 ; SW39.2@1183.16,2446.35 cw(c1179.98,2427.44) SW39.2@1195.6,2438.57 ; D4.K2@1204.75,2731.94 cw(c1191.3,2718.5) 1210.31,2718.5 cw(c1229.32,2718.5) D4.K2@1215.88,2731.94
NetSW40_2: D8.K1 SW40.2 | length 719
  Top Layer w15.75: v1(1931.84,2370.23) v1(1931.84,2396.9) v1(1931.84,2423.57) v1(1931.84,2450.23)
  Bottom Layer w15.75: SW40.2@1930.58,2362.99 cw(c1930.58,2248.93) 2011.23,2329.58 ; SW40.2@1930.58,2378.74 cw(c1930.58,2302.7) 1984.35,2356.47 ; SW40.2@1931.84,2392.96 cw(c1931.84,2354.31) SW40.2@1959.17,2381.64 ; SW40.2@1934.42,2367.26 cw(c1949.46,2349.91) SW40.2@1955.4,2372.09 ; SW40.2@1935.25,2372.2 ccw(c1965.14,2389.46) SW40.2@1956.21,2356.12 ; SW40.2@1937.88,2402.94 2110.61,2230.2 D8.K1@2110.61,2116.94 ; SW40.2@1967.98,2400.39 ccw(c2034.52,2400.39) 1987.47,2353.35
NetSW41_2: D11.K1 SW41.2 | length 551.9
  Top Layer w15.75: v1(2679.87,2370.23) v1(2679.87,2396.9) v1(2679.87,2423.57) v1(2679.87,2450.23)
  Bottom Layer w15.75: SW41.2@2660.76,2367.53 cw(c2647.86,2343.78) 2674.88,2343.78 cw(c2697,2343.78) SW41.2@2690.17,2364.82 ; 2674.88,2348.68 cw(c2701.43,2348.68) SW41.2@2682.66,2367.45 ; SW41.2@2674.88,2370.23 2674.88,2343.9 2723.11,2295.68 2832.92,2295.68 2859.8,2268.8 D11.K1@2859.8,2116.94
NetSW42_2: D14.K1 SW42.2 | length 771.2
  Top Layer w15.75: v1(3427.91,2370.23) v1(3427.91,2396.9) v1(3427.91,2423.57) v1(3427.91,2450.23)
  Bottom Layer w15.75: SW42.2@3402.07,2372.2 cw(c3356.48,2319.89) 3425.87,2319.89 ; SW42.2@3412.42,2384.07 cw(c3386.65,2354.51) 3425.87,2354.51 ; SW42.2@3412.64,2383.76 ccw(c3432.2,2398.09) SW42.2@3428.51,2374.13 ; SW42.2@3424.71,2367.94 cw(c3413.87,2360.17) SW42.2@3426.82,2357 ; SW42.2@3425.05,2367.53 cw(c3403.35,2346.99) 3431.72,2337.64 ; 3425.87,2353.09 cw(c3465.29,2353.09) SW42.2@3440.35,2383.62 ; SW42.2@3425.87,2355.8 cw(c3442.33,2355.8) SW42.2@3430.69,2367.45 ; SW42.2@3425.87,2370.23 3425.87,2319.89 ; SW42.2@3427.5,2374.15 ccw(c3426.11,2387.68) SW42.2@3436.66,2379.1 ; SW42.2@3436.48,2378.35 cw(c3425.11,2367.59) SW42.2@3439.98,2362.69 ; SW42.2@3450.31,2371.43 ccw(c3492.42,2319.89) 3425.87,2319.89 ; D14.K1@3608.64,2116.94 3608.64,2260.76 3588.76,2280.64 3465.12,2280.64 3425.87,2319.89
NetSW43_2: D17.K1 SW43.2 | length 395.3
  Top Layer w15.75: v1(4175.94,2423.57) v1(4175.94,2450.23)
  Bottom Layer w15.75: SW43.2@4174.68,2410.23 4174.68,2329.24 4356.47,2147.45 D17.K1@4356.47,2116.94
  other v1: 4175.94,2370.23 4175.94,2396.9
NetSW44_2: D20.K1 SW44.2 | length 394.2
  Top Layer w15.75: v1(4923.97,2423.57) v1(4923.97,2450.23)
  Bottom Layer w15.75: SW44.2@4922.71,2410.23 4922.71,2400.39 5101.98,2221.12 D20.K1@5101.98,2116.94
  other v1: 4923.97,2370.23 4923.97,2396.9
NetSW45_2: D23.K1 SW45.2 | length 421.8
  Top Layer w15.75: v1(5672,2370.23) v1(5672,2396.9) ; v1(5672,2423.57) v1(5672,2450.23)
  Bottom Layer w15.75: SW45.2@5670.74,2410.23 5852.19,2228.78 D23.K1@5852.19,2116.94
NetSW46_2: D26.K1 SW46.2 | length 394.9
  Top Layer w15.75: v1(6420.03,2423.57) v1(6420.03,2450.23)
  Bottom Layer w15.75: SW46.2@6418.77,2410.23 6418.77,2398.38 6599.67,2217.48 D26.K1@6599.67,2116.94
  other v1: 6420.03,2370.23 6420.03,2396.9
NetSW47_2: D29.K1 SW47.2 | length 734.6
  Top Layer w15.75: v1(7168.06,2370.23) v1(7168.06,2396.9) v1(7168.06,2423.57) v1(7168.06,2450.23)
  Bottom Layer w15.75: SW47.2@7140.36,2373.94 cw(c7076.51,2310.1) 7166.8,2310.1 cw(c7257.1,2310.1) SW47.2@7193.25,2373.94 ; SW47.2@7151.24,2385.45 ccw(c7173.7,2400.95) SW47.2@7168.77,2374.11 ; SW47.2@7151.49,2385.08 cw(c7114.53,2348.12) 7166.8,2348.12 cw(c7219.08,2348.12) SW47.2@7182.11,2385.08 ; SW47.2@7165.23,2367.5 cw(c7155.89,2358.51) SW47.2@7168.52,2355.6 ; SW47.2@7166.8,2357.69 cw(c7180.61,2357.69) SW47.2@7170.85,2367.45 ; SW47.2@7166.8,2370.23 7166.8,2292.76 7246.51,2213.05 7318.5,2213.05 7347.76,2183.79 D29.K1@7347.76,2116.94 ; SW47.2@7167.41,2374.12 ccw(c7164.23,2393.03) SW47.2@7179.85,2381.9
NetSW48_2: D32.K1 SW48.2 | length 741.5
  Top Layer w15.75: v1(7916.09,2370.23) v1(7916.09,2396.9) v1(7916.09,2423.57) v1(7916.09,2450.23)
  Bottom Layer w15.75: SW48.2@7888.71,2373.62 cw(c7828.22,2311.63) 7914.83,2311.63 ; SW48.2@7899.61,2385.04 ccw(c7921.39,2400.3) SW48.2@7916.78,2374.11 ; SW48.2@7899.71,2384.89 cw(c7864.69,2349.01) 7914.83,2349.01 cw(c7964.98,2349.01) SW48.2@7929.96,2384.89 ; SW48.2@7913.28,2367.48 cw(c7904.46,2358.87) SW48.2@7916.47,2356.09 ; SW48.2@7914.83,2357.69 cw(c7928.64,2357.69) SW48.2@7918.88,2367.45 ; SW48.2@7914.83,2370.23 7914.83,2311.63 ; SW48.2@7915.47,2374.12 ccw(c7912.52,2392.43) SW48.2@7927.55,2381.57 ; SW48.2@7940.96,2373.62 ccw(c8001.45,2311.63) 7914.83,2311.63 ; D32.K1@8094.77,2116.94 8094.77,2228.81 8075.36,2248.23 7978.24,2248.23 7914.83,2311.63
NetSW49_2: D35.K1 SW49.2 | length 628.9
  Top Layer w15.75: v1(8664.12,2370.23) v1(8664.12,2396.9) v1(8664.12,2423.57) v1(8664.12,2450.23)
  Bottom Layer w15.75: SW49.2@8640.26,2370.59 cw(c8605.75,2325.08) 8662.87,2325.08 ; SW49.2@8661.54,2367.27 cw(c8645.79,2349.22) 8668.46,2341.5 ; SW49.2@8662.87,2357.69 cw(c8676.67,2357.69) SW49.2@8666.91,2367.45 ; SW49.2@8662.87,2370.23 8662.87,2325.08 ; SW49.2@8671.89,2379.13 cw(c8662.47,2368.34) SW49.2@8676.03,2363.72 ; SW49.2@8685.47,2370.59 ccw(c8719.98,2325.08) 8662.87,2325.08 ; D35.K1@8843.66,2116.94 8843.66,2245.62 8831.29,2257.98 8729.96,2257.98 8662.87,2325.08
NetSW50_2: D38.K1 SW50.2 | length 456.6
  Top Layer w11.81: v1(9412.16,2423.57) v1(9412.16,2450.23)
  Bottom Layer w15.75: SW50.2@9410.9,2410.23 9410.9,2321.89 9456.08,2276.71 9561.49,2276.71 9591.76,2246.45 D38.K1@9591.76,2116.94
  other v1: 9412.16,2370.23 9412.16,2396.9
NetSW51_2: D41.K1
NetSW52_2: D44.K2 SW52.2 | length 1005.8
  Top Layer w15.75: v1(11275.92,3108.74) 11363.85,3020.81 v1(11449.59,3020.81) ; v1@11485.98,2377.12 v1(11485.98,2396.9) v1(11485.98,2423.57) v1(11485.98,2450.23)
  Bottom Layer w15.75: D44.K2@11210.03,3108.74 v1(11275.92,3108.74) ; v1(11449.59,3020.81) 11567.66,2902.74 11567.66,2705.87 11477.83,2616.03 SW52.2@11477.83,2450.23
  other v1: 11485.98,2370.23
NetSW53_2: D47.K2 SW53.2 | length 409.3
  Top Layer w15.75: v1@12234.01,2377.12 v1(12234.01,2396.9) v1(12234.01,2423.57) v1(12234.01,2450.23)
  Bottom Layer w15.75: SW53.2@12225.86,2450.23 12225.86,2701.97 12261.4,2737.51 D47.K2@12295.59,2737.51
  other v1: 12234.01,2370.23
NetSW54_2: D50.K2 SW54.2 | length 409.5
  Top Layer w15.75: v1@12982.04,2377.12 v1(12982.04,2396.9) v1(12982.04,2423.57) v1(12982.04,2450.23)
  Bottom Layer w15.75: SW54.2@12973.89,2450.23 12973.89,2703.94 13007.46,2737.51 D50.K2@13042.64,2737.51
  other v1: 12982.04,2370.23
NetSW55_2: D52.K2 SW55.2 | length 388.3
  Top Layer w15.75: v1@13930.86,2375.16 v1(13930.86,2396.9) v1(13930.86,2423.57) v1(13930.86,2450.23)
  Bottom Layer w15.75: SW55.2@13924.68,2450.23 13924.68,2641.44 13986.22,2702.98 D52.K2@13986.22,2738.01
  other v1: 13930.86,2370.23
NetSW56_2: D54.K2 SW56.2 | length 411.4
  Top Layer w15.75: v1@14678.89,2375.16 v1(14678.89,2396.9) v1(14678.89,2423.57) v1(14678.89,2450.23)
  Bottom Layer w15.75: SW56.2@14672.71,2450.23 14672.71,2703.94 14706.28,2737.51 D54.K2@14741.46,2737.51
  other v1: 14678.89,2370.23
NetSW57_2: D57.K2 SW57.2 | length 419.9
  Top Layer w15.75: v1@15426.92,2375.16 v1(15426.92,2396.9) v1(15426.92,2423.57) v1(15426.92,2450.23)
  Bottom Layer w15.75: SW57.2@15420.74,2450.23 15420.74,2667.3 15449.49,2696.05 D57.K2@15449.49,2783.15
  other v1: 15426.92,2370.23
NetSW58_2: D60.K2 SW58.2 | length 410.5
  Top Layer w15.75: v1(16174.95,1996.22) v1(16174.95,2022.89) v1(16174.95,2049.55) v1@16174.95,2071.3
  Bottom Layer w15.75: SW58.2@16168.77,2076.22 16168.77,2328.94 16202.34,2362.51 D60.K2@16237.52,2362.51
  other v1: 16174.95,2076.22
NetSW59_2: D2.K2 SW59.2 | length 727.5
  Top Layer w15.75: v1(342.28,1622.2) v1(342.28,1648.87) v1(342.28,1675.54) v1(342.28,1702.2)
  Bottom Layer w15.75: SW59.2@314.57,1698.49 ccw(c250.72,1762.34) 341.02,1762.34 ccw(c431.31,1762.34) SW59.2@367.46,1698.49 ; SW59.2@325.45,1686.99 cw(c347.91,1671.49) SW59.2@342.99,1698.33 ; SW59.2@325.7,1687.36 ccw(c288.74,1724.32) 341.02,1724.32 ccw(c393.29,1724.32) SW59.2@356.33,1687.36 ; SW59.2@339.44,1704.93 ccw(c330.1,1713.93) SW59.2@342.74,1716.84 ; SW59.2@341.02,1702.2 341.02,1908.26 397.95,1965.19 D2.K2@397.95,2041.94 ; SW59.2@341.01,1714.75 ccw(c354.82,1714.75) SW59.2@345.06,1704.99 ; SW59.2@341.62,1698.32 cw(c338.44,1679.41) SW59.2@354.06,1690.53
NetSW60_2: D5.K2 SW60.2 | length 419.7
  Top Layer w15.75: v1(1370.82,1622.2) v1(1370.82,1648.87) v1(1370.82,1675.54) v1(1370.82,1702.2)
  Bottom Layer w15.75: SW60.2@1361.48,1702.2 D5.K2@1361.48,2041.94
NetSW61_2: D8.K2 SW61.2 | length 419.7
  Top Layer w15.75: v1(2118.85,1622.2) v1(2118.85,1648.87) v1(2118.85,1675.54) v1(2118.85,1702.2)
  Bottom Layer w15.75: SW61.2@2110.61,1702.2 D8.K2@2110.61,2041.94
NetSW62_2: D11.K2 SW62.2 | length 419.7
  Top Layer w15.75: v1(2866.88,1622.2) v1(2866.88,1648.87) v1(2866.88,1675.54) v1(2866.88,1702.2)
  Bottom Layer w15.75: SW62.2@2859.8,1702.2 D11.K2@2859.8,2041.94
NetSW63_2: D14.K2 SW63.2 | length 419.7
  Top Layer w15.75: v1(3614.91,1622.2) v1(3614.91,1648.87) v1(3614.91,1675.54) v1(3614.91,1702.2)
  Bottom Layer w15.75: SW63.2@3608.64,1702.2 D14.K2@3608.64,2041.94
NetSW64_2: D17.K2 SW64.2 | length 419.7
  Top Layer w15.75: v1(4362.94,1622.2) v1(4362.94,1648.87) v1(4362.94,1675.54) v1(4362.94,1702.2)
  Bottom Layer w15.75: SW64.2@4356.47,1702.2 D17.K2@4356.47,2041.94
NetSW65_2: D20.K2 SW65.2 | length 419.7
  Top Layer w15.75: v1(5110.98,1622.2) v1(5110.98,1648.87) v1(5110.98,1675.54) v1(5110.98,1702.2)
  Bottom Layer w15.75: SW65.2@5101.98,1702.2 D20.K2@5101.98,2041.94
NetSW66_2: D23.K2 SW66.2 | length 707
  Top Layer w15.75: v1(5859.01,1622.2) v1(5859.01,1648.87) v1(5859.01,1675.54) v1(5859.01,1702.2)
  Bottom Layer w15.75: SW66.2@5831.3,1698.49 ccw(c5767.45,1762.34) 5857.75,1762.34 ccw(c5948.04,1762.34) SW66.2@5884.19,1698.49 ; SW66.2@5842.18,1686.99 cw(c5864.64,1671.49) SW66.2@5859.72,1698.33 ; SW66.2@5842.44,1687.36 ccw(c5805.47,1724.32) 5857.75,1724.32 ccw(c5910.02,1724.32) SW66.2@5873.06,1687.36 ; D23.K2@5848.5,2041.26 5857.75,2032.02 SW66.2@5857.75,1702.2 ; SW66.2@5856.17,1704.93 ccw(c5846.84,1713.93) SW66.2@5859.47,1716.84 ; SW66.2@5857.75,1714.75 ccw(c5871.55,1714.75) SW66.2@5861.79,1704.99 ; SW66.2@5858.35,1698.32 cw(c5855.18,1679.41) SW66.2@5870.79,1690.53
NetSW67_2: D26.K2 SW67.2 | length 419.7
  Top Layer w15.75: v1(6607.04,1622.2) v1(6607.04,1648.87) v1(6607.04,1675.54) v1(6607.04,1702.2)
  Bottom Layer w15.75: SW67.2@6599.67,1702.2 D26.K2@6599.67,2041.94
NetSW68_2: D29.K2 SW68.2 | length 419.7
  Top Layer w15.75: v1(7355.07,1622.2) v1(7355.07,1648.87) v1(7355.07,1675.54) v1(7355.07,1702.2)
  Bottom Layer w15.75: SW68.2@7347.76,1702.2 D29.K2@7347.76,2041.94
NetSW69_2: D32.K2 SW69.2 | length 450.7
  Top Layer w15.75: v1(8103.1,1622.2) v1(8103.1,1648.87) v1(8103.1,1675.54) v1(8103.1,1702.2)
  Bottom Layer w15.75: SW69.2@8099.66,1704.12 ccw(c8083.86,1712.91) 8101.25,1717.87 ; D32.K2@8101.28,2041.94 8101.28,1699.66 8102.65,1698.29 cw(c8100.86,1682.78) SW69.2@8113.09,1692.48
NetSW70_2: D35.K2 SW70.2 | length 419.7
  Top Layer w15.75: v1(8851.13,1622.2) v1(8851.13,1648.87) v1(8851.13,1675.54) v1(8851.13,1702.2)
  Bottom Layer w15.75: SW70.2@8843.66,1702.2 D35.K2@8843.66,2041.94
NetSW71_2: D41.K2 SW51.2 | length 368.3
  Top Layer w15.75: v1@10440.26,1996.16 10442.67,1998.57 v1(10442.67,2022.89) v1(10442.67,2049.55) v1(10442.67,2076.22)
  Bottom Layer w15.75: SW51.2@10439,2076.22 D41.K2@10439,2363.49
  other v1: 10442.67,1996.22
NetSW72_2: D53.K1 SW72.2 | length 397.6
  Top Layer w11.81: v1(13930.86,1675.54) v1(13930.86,1702.2)
  Bottom Layer w15.75: SW72.2@13929.6,1662.2 13929.6,1592.14 13993.42,1528.32 D53.K1@13993.42,1317.68
  other v1: 13930.86,1622.2 13930.86,1648.87
NetSW73_2: D55.K1 SW73.2 | length 411.3
  Top Layer w11.81: v1(14678.89,1622.2) v1(14678.89,1648.87) v1(14678.89,1675.54) v1(14678.89,1702.2)
  Bottom Layer w15.75: SW73.2@14677.63,1622.2 14677.63,1580.33 14742.44,1515.52 D55.K1@14742.44,1317.78
NetSW74_2: D58.K1 SW74.2 | length 409.9
  Top Layer w11.81: v1(15426.92,1622.2) v1(15426.92,1648.87) v1(15426.92,1675.54) v1(15426.92,1702.2)
  Bottom Layer w15.75: SW74.2@15425.66,1622.2 15425.66,1586.24 15489.49,1522.41 D58.K1@15489.49,1318.77
NetSW75_2: D3.K1 SW75.2 | length 798.7
  Top Layer w15.75: v1@155.27,874.36 v1@155.27,954.36
  Bottom Layer w15.75: SW75.2@130.16,875.7 cw(c88.2,825.01) 154.01,825.01 ; SW75.2@140.2,887.83 cw(c115.91,858.48) 154.01,858.48 cw(c192.11,858.48) SW75.2@167.81,887.83 ; SW75.2@141.08,886.69 ccw(c158.6,900.21) SW75.2@155.77,878.26 ; SW75.2@152.6,871.46 cw(c134.37,851.7) 159.96,843.44 ; SW75.2@154.01,861.81 cw(c167.81,861.81) SW75.2@158.05,871.57 ; SW75.2@154.01,886.9 ccw(c167.81,886.9) SW75.2@158.05,877.14 ; SW75.2@154.01,888.48 cw(c167.81,888.48) SW75.2@158.05,898.24 ; SW75.2@154.01,913.57 ccw(c167.81,913.57) SW75.2@158.05,903.81 ; SW75.2@154.01,914.36 154.01,825 ; SW75.2@154.81,878.27 ccw(c153.14,892.69) SW75.2@164.52,883.68 ; SW75.2@163.28,883.04 cw(c152.77,871.64) SW75.2@167.52,866.88 ; SW75.2@177.85,875.7 ccw(c219.81,825.01) 154.01,825.01 ; D3.K1@191.12,573.6 ccw(c177.68,587.04) 196.69,587.04 ccw(c215.7,587.04) D3.K1@202.26,573.6 ; D3.K1@196.69,568.03 196.69,782.32 154.01,825 ; SW75.2@154.01,915.14 cw(c167.81,915.14) 158.05,924.9 ccw(c167.81,915.14) SW75.2@154.01,915.14
  other v1: 155.27,874.17 155.27,900.84 155.27,927.5 155.27,954.17
NetSW76_2: D9.K1 SW76.2 | length 641
  Top Layer w15.75: v1@1749.76,879.09 v1(1749.76,900.84) v1(1749.76,927.5) v1(1749.76,954.17)
  Bottom Layer w15.75: SW76.2@1743.57,874.17 1743.57,641.94 1761.11,624.4 2008.15,624.4 2023.64,608.91 D9.K1@2023.64,568.93
  other v1: 1749.76,874.17
NetSW77_2: D12.K2 SW77.2 | length 389.9
  Top Layer w15.75: v1@2497.79,879.09 v1(2497.79,900.84) v1(2497.79,927.5) v1(2497.79,954.17)
  Bottom Layer w15.75: SW77.2@2491.9,954.17 D12.K2@2491.9,1268.97
  other v1: 2497.79,874.17
NetSW78_2: D15.K2 SW78.2 | length 389.9
  Top Layer w15.75: v1@3245.82,879.09 v1(3245.82,900.84) v1(3245.82,927.5) v1(3245.82,954.17)
  Bottom Layer w15.75: SW78.2@3236.32,954.17 D15.K2@3236.32,1268.97
  other v1: 3245.82,874.17
NetSW79_2: D18.K2 SW79.2 | length 389.9
  Top Layer w15.75: v1@3993.85,879.09 v1(3993.85,900.84) v1(3993.85,927.5) v1(3993.85,954.17)
  Bottom Layer w15.75: SW79.2@3985.77,954.17 D18.K2@3985.77,1268.97
  other v1: 3993.85,874.17
NetSW80_2: D21.K1 SW80.2 | length 283.9
  Top Layer w15.75: v1(4741.88,927.5) v1(4741.88,954.17)
  Bottom Layer w15.75: SW80.2@4740.62,914.17 4740.62,667.49 D21.K1@4748.09,660.03
  other v1: 4741.88,874.17 4741.88,900.84
NetSW81_2: D24.K2 SW81.2 | length 389.9
  Top Layer w15.75: v1@5489.91,879.09 v1(5489.91,900.84) v1(5489.91,927.5) v1(5489.91,954.17)
  Bottom Layer w15.75: SW81.2@5482.79,954.17 D24.K2@5482.79,1268.97
  other v1: 5489.91,874.17
NetSW82_2: D27.K2 SW82.2 | length 389.9
  Top Layer w15.75: v1@6237.94,879.09 v1(6237.94,900.84) v1(6237.94,927.5) v1(6237.94,954.17)
  Bottom Layer w15.75: SW82.2@6231.76,954.17 D27.K2@6231.76,1268.97
  other v1: 6237.94,874.17
NetSW83_2: D30.K2 SW83.2 | length 379
  Top Layer w15.75: v1@6985.98,879.09 v1(6985.98,900.84)
  Bottom Layer w15.75: D30.K2@6978.85,1268.97 6978.85,920.03 SW83.2@6984.72,914.17
  other v1: 6985.98,874.17 6985.98,927.5 6985.98,954.17
NetSW84_2: D33.K1 SW84.2 | length 400.2
  Top Layer w15.75: v1@7734.01,879.09 v1(7734.01,900.84) v1(7734.01,927.5) v1(7734.01,954.17)
  Bottom Layer w15.75: D33.K1@7682.81,567.73 7682.92,567.84 7682.92,716.26 7727.83,761.16 SW84.2@7727.83,874.17
  other v1: 7734.01,874.17
NetSW85_2: D36.K1 SW85.2 | length 417.8
  Top Layer w15.75: v1@8482.04,879.09 v1(8482.04,900.84) v1(8482.04,927.5) v1(8482.04,954.17)
  Bottom Layer w15.75: SW85.2@8475.86,874.17 8475.86,799.4 8568.54,706.71 D36.K1@8568.54,569.79
  other v1: 8482.04,874.17
NetSW86_2: D42.K1 SW86.2 | length 535.7
  Top Layer w15.75: v1@9879.68,874.17 9883.61,878.11 v1(9883.61,900.84) v1(9883.61,927.5) v1(9883.61,954.17)
  Bottom Layer w15.75: v1(9883.61,874.17) 9883.61,810.93 10083,611.54 D42.K1@10083,502.67
NetSW87_2: D48.K1 SW87.2 | length 339.9
  Top Layer w15.75: v1(12234.01,874.17) v1(12234.01,900.84) v1(12234.01,927.5) v1(12234.01,954.17)
  Bottom Layer w15.75: SW87.2@12232.75,874.17 12232.75,831.49 12293.62,770.62 D48.K1@12293.62,639.45
NetSW88_2: D53.K2 SW88.2 | length 444
  Top Layer w15.75: v1@13925.94,874.17 13930.86,879.09 v1(13930.86,900.84) v1(13930.86,927.5) v1(13930.86,954.17)
  Bottom Layer w15.75: SW88.2@13924.68,954.17 13924.68,1202.95 13963.17,1241.44 D53.K2@13992.09,1241.44 ; D53.K2@13982.58,1235.88 ccw(c13969.14,1222.44) 13969.14,1241.44 ccw(c13969.14,1260.45) D53.K2@13982.58,1247.01
  other v1: 13930.86,874.17
NetSW89_2: D55.K2 SW89.2 | length 412.2
  Top Layer w15.75: v1@14678.89,879.09 v1(14678.89,900.84) v1(14678.89,927.5) v1(14678.89,954.17)
  Bottom Layer w15.75: SW89.2@14672.71,954.17 14672.71,1209.84 14704.31,1241.44 D55.K2@14741.1,1241.44
  other v1: 14678.89,874.17
NetSW90_2: D58.K2 SW90.2 | length 411.1
  Top Layer w15.75: v1@15426.92,879.09 v1(15426.92,900.84) v1(15426.92,927.5) v1(15426.92,954.17)
  Bottom Layer w15.75: SW90.2@15420.74,954.17 15420.74,1208.86 15454.31,1242.43 D58.K2@15488.15,1242.43
  other v1: 15426.92,874.17
NetSW91_2: D61.K2 SW91.2 | length 405.9
  Top Layer w15.75: v1(16174.95,500.16) v1(16174.95,526.82) v1(16174.95,553.49) v1@16174.95,575.24
  Bottom Layer w15.75: SW91.2@16168.77,580.16 16168.77,836.81 16198.4,866.44 D61.K2@16230.63,866.44
  other v1: 16174.95,580.16
NetSW92_2: D3.K2 SW92.2 | length 698.6
  Top Layer w15.75: v1(155.27,126.14) v1(155.27,152.81) v1(155.27,179.47) v1(155.27,206.14)
  Bottom Layer w15.75: SW92.2@127.56,202.43 ccw(c63.71,266.28) 154.01,266.28 ccw(c244.3,266.28) SW92.2@180.45,202.43 ; SW92.2@138.44,190.92 cw(c160.9,175.43) SW92.2@155.98,202.27 ; SW92.2@138.7,191.29 ccw(c101.73,228.26) 154.01,228.26 ccw(c206.28,228.26) SW92.2@169.32,191.29 ; SW92.2@152.43,208.87 ccw(c143.1,217.87) SW92.2@155.73,220.77 ; SW92.2@154.01,206.14 154.01,405.76 196.69,448.44 D3.K2@196.69,493.03 ; SW92.2@154.01,218.69 ccw(c167.81,218.69) SW92.2@158.05,208.92 ; SW92.2@154.61,202.26 cw(c151.44,183.35) SW92.2@167.05,194.47 ; D3.K2@191.12,487.46 cw(c177.68,474.02) 196.69,474.02 cw(c215.7,474.02) D3.K2@202.26,487.46
NetSW93_2: D6.K2 SW93.2 | length 384.1
  Top Layer w15.75: v1@1090.31,126.14 1092.27,128.11 v1(1092.27,152.81) v1(1092.27,179.47) v1(1092.27,206.14)
  Bottom Layer w15.75: SW93.2@1089.05,206.14 1089.05,398.67 1130,439.63 D6.K2@1130,492.5
  other v1: 1092.27,126.14
NetSW94_2: D9.K2 SW94.2 | length 368.9
  Top Layer w15.75: v1@2025.35,126.14 2029.28,130.08 v1(2029.28,152.81) v1(2029.28,179.47) v1(2029.28,206.14)
  Bottom Layer w15.75: SW94.2@2024.09,206.14 D9.K2@2024.09,493.41
  other v1: 2029.28,126.14
NetSW95_2: D21.K2 SW95.2 | length 814.2
  Top Layer w15.75: v1(4830.46,126.14) v1(4830.46,152.81) v1(4830.46,179.47) v1(4830.46,206.14)
  Bottom Layer w15.75: D21.K2@4742.33,586.25 4800.22,586.25 4829.2,557.27 SW95.2@4829.2,206.14 ; SW95.2@4802.76,202.43 ccw(c4738.91,266.28) 4829.2,266.28 ccw(c4919.5,266.28) SW95.2@4855.65,202.43 ; SW95.2@4813.64,190.92 cw(c4836.1,175.43) SW95.2@4831.17,202.27 ; SW95.2@4813.89,191.29 ccw(c4776.93,228.26) 4829.2,228.26 ccw(c4881.48,228.26) SW95.2@4844.52,191.29 ; SW95.2@4827.63,208.87 ccw(c4818.29,217.87) SW95.2@4830.93,220.77 ; SW95.2@4829.2,218.69 ccw(c4843.01,218.69) SW95.2@4833.25,208.92 ; SW95.2@4829.81,202.26 cw(c4826.63,183.35) SW95.2@4842.25,194.47
NetSW96_2: D33.K2 SW96.2 | length 388.3
  Top Layer w15.75: v1(7631.65,206.14) v1(7631.65,179.47) v1(7631.65,152.81) 7631.65,130.08 v1@7635.58,126.14
  Bottom Layer w15.75: SW96.2@7634.32,206.14 7634.32,413.48 7682.81,461.97 D33.K2@7682.81,492.73
  other v1: 7631.65,126.14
